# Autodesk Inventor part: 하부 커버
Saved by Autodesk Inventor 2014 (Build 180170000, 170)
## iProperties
Created: 2026-08
Part Number: 하부 커버
Material: 알루미늄 6061
Document SubType Name: Modeling
Designer: dg
Density: 2.71 g/cm^3
Appearance: 알루미늄 - 평지
Mass: 55.5689 g
Surface Area: 66.8036 cm^2
Volume: 20.5051 cm^3
Author: jhkim
Creation Date: 2026-07-31
Sending System: Autodesk Inventor 2027
Preprocessor: ST-DEVELOPER v20.1
Author: dg
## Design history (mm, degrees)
node "하부 커버1"
node "솔리드1"
node "기준1"
